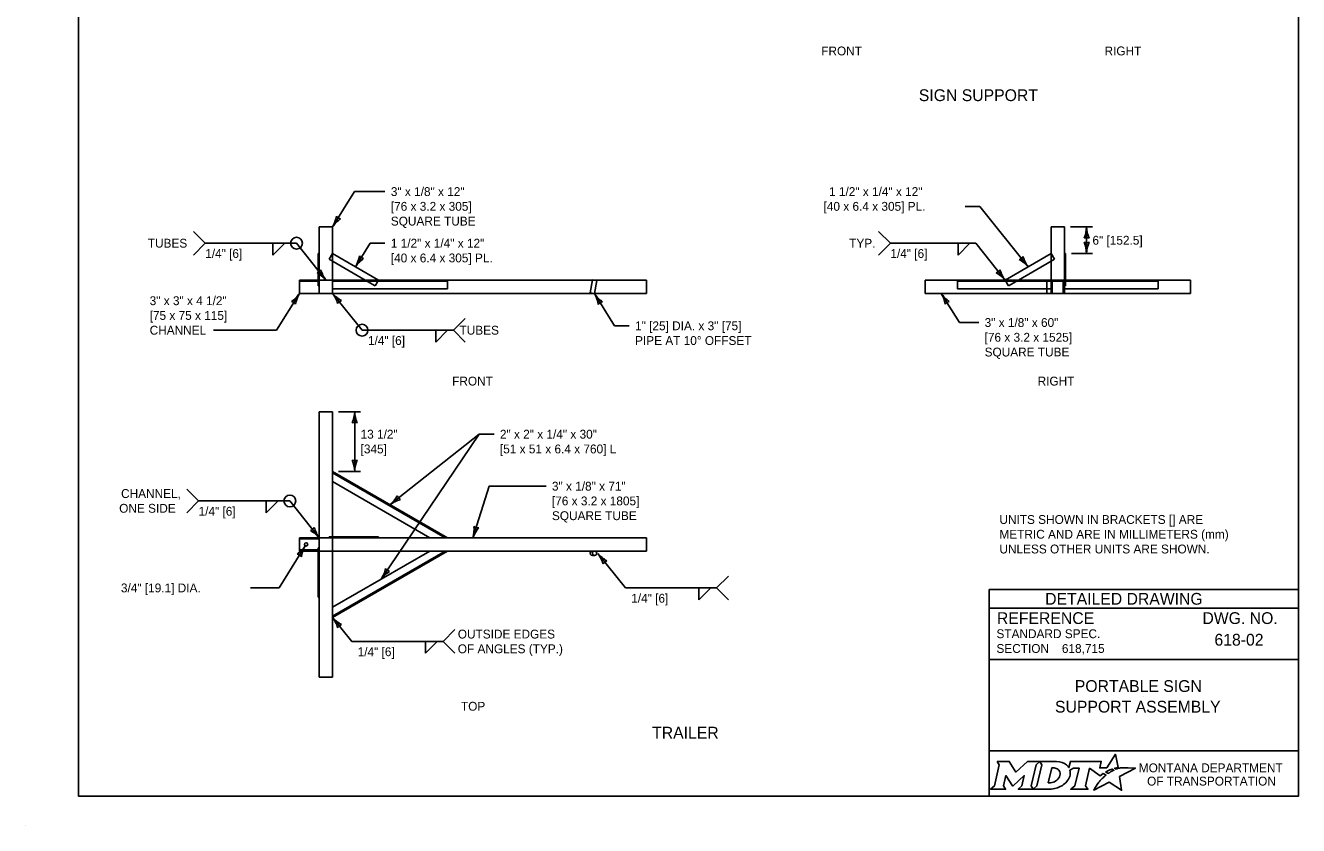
# Model space of a CAD drawing. Extents: x 49991.4 to 50021, y 49987.6 to 50011.4.
# Drawn here: x 49999.98 to 50008.61, y 49999.86 to 50005.29 of the extents above; entities that cross this region are included whole.
import ezdxf

# ---------------------------------------------------------------- set-up
doc = ezdxf.new("R2010")
doc.units = 0
for name, color, linetype in [('Level 1', 7, 'Continuous'), ('Level 2', 7, 'Continuous'), ('Level 3', 7, 'Continuous'), ('Level 4', 7, 'Continuous')]:
    doc.layers.add(name, color=color, linetype=linetype)

msp = doc.modelspace()

# ---------------------------------------------------------------- linework, layer by layer
at = {"layer": 'Level 1'}
for p, q in [((50001.9705, 50003.9214), (50001.9705, 50003.4714)), ((50001.9705, 50003.9214), (50002.0605, 50003.9214)), ((50002.0605, 50003.9214), (50002.0605, 50003.7414)), ((50006.9363, 50003.4714), (50006.9363, 50003.9214)), ((50006.9363, 50003.9214), (50007.0263, 50003.9214)), ((50007.0263, 50003.4714), (50007.0263, 50003.9214)), ((50001.9705, 50003.7414), (50001.9631, 50003.7414)), ((50001.9631, 50003.7414), (50001.9631, 50003.5224)), ((50002.0605, 50003.7414), (50002.0381, 50003.7023)), ((50002.0605, 50003.7414), (50002.3724, 50003.5614)), ((50006.9363, 50003.7414), (50006.6244, 50003.5614)), ((50007.0263, 50003.7414), (50007.0337, 50003.7414)), ((50007.0338, 50003.7414), (50007.0338, 50003.5614)), ((50002.0381, 50003.7023), (50002.2823, 50003.5614)), ((50002.0605, 50003.6894), (50002.0605, 50003.4714)), ((50006.9363, 50003.6894), (50006.7145, 50003.5614)), ((50001.8355, 50003.5614), (50001.8355, 50003.4714)), ((50003.8232, 50003.5614), (50001.8355, 50003.5614)), ((50001.9705, 50003.5224), (50001.9631, 50003.5224)), ((50002.0605, 50003.5014), (50002.8399, 50003.5014)), ((50002.8399, 50003.5014), (50002.8399, 50003.5614)), ((50003.8236, 50003.5633), (50003.8079, 50003.4746)), ((50003.8236, 50003.5633), (50003.8531, 50003.5581)), ((50004.1905, 50003.5614), (50003.8345, 50003.5614)), ((50003.8531, 50003.5581), (50003.8375, 50003.4694)), ((50004.1905, 50003.5614), (50004.1905, 50003.4714)), ((50007.8813, 50003.5614), (50006.0813, 50003.5614)), ((50006.0813, 50003.5614), (50006.0813, 50003.4714)), ((50006.2999, 50003.5014), (50006.2999, 50003.5614)), ((50006.9063, 50003.5014), (50006.2999, 50003.5014)), ((50006.9063, 50003.4714), (50006.9063, 50003.5614)), ((50007.0263, 50003.5014), (50007.6626, 50003.5014)), ((50007.6626, 50003.5014), (50007.6626, 50003.5614)), ((50007.8813, 50003.5614), (50007.8813, 50003.4714)), ((50003.8266, 50003.4714), (50001.8355, 50003.4714)), ((50003.8079, 50003.4746), (50003.8375, 50003.4694)), ((50004.1905, 50003.4714), (50003.8378, 50003.4714)), ((50007.8813, 50003.4714), (50006.0813, 50003.4714)), ((50002.0605, 50002.6686), (50001.9705, 50002.6686)), ((50001.9705, 50002.6686), (50001.9705, 50000.8686)), ((50002.0605, 50000.8686), (50002.0605, 50002.6686)), ((50002.0605, 50002.2636), (50002.8399, 50001.8136)), ((50002.0605, 50002.1944), (50002.7199, 50001.8136)), ((50004.1905, 50001.8136), (50001.8355, 50001.8136)), ((50001.8355, 50001.7236), (50001.8355, 50001.8136)), ((50002.0381, 50001.8211), (50002.0381, 50001.8136)), ((50002.0381, 50001.8211), (50002.3724, 50001.8211)), ((50002.3724, 50001.8211), (50002.3724, 50001.8136)), ((50004.1905, 50001.7236), (50004.1905, 50001.8136)), ((50001.8355, 50001.7236), (50004.1905, 50001.7236)), ((50001.9705, 50001.7461), (50001.9631, 50001.7461)), ((50001.9631, 50001.4118), (50001.9631, 50001.7461)), ((50002.0605, 50001.2736), (50002.8399, 50001.7236)), ((50002.0605, 50001.3429), (50002.7199, 50001.7236)), ((50003.8383, 50001.6936), (50003.8236, 50001.6936)), ((50001.9705, 50001.4118), (50001.9631, 50001.4118)), ((50001.9705, 50000.8686), (50002.0605, 50000.8686)), ((49999.9766, 49999.8624), (49999.9766, 49999.8624))]:
    msp.add_line(p, q, dxfattribs=at)
msp.add_lwpolyline([(50008.6146, 50011.2628), (50000.3356, 50011.2628), (50000.3356, 50000.0624), (50008.6146, 50000.0624)], close=True, dxfattribs=at)
msp.add_circle((50001.8806, 50001.7686), 0.0113, dxfattribs=at)
msp.add_ellipse((50003.8227, 50001.7086), major_axis=(0, 0.015), ratio=0.9848, start_param=6.22507, end_param=9.482803, dxfattribs=at)
msp.add_ellipse((50003.8383, 50001.7086), major_axis=(0, 0.015), ratio=0.9848, dxfattribs=at)
at = {"layer": 'Level 2'}
for p, q in [((50008.6146, 50001.4624), (50006.5146, 50001.4624)), ((50006.5146, 50001.4624), (50006.5146, 50000.0624)), ((50008.6146, 50001.3374), (50006.5146, 50001.3374)), ((50008.2507, 50001.1223), (50008.2507, 50001.1223)), ((50008.6146, 50000.9874), (50006.5146, 50000.9874)), ((50007.0089, 50001.0629), (50007.0089, 50001.0629)), ((50007.5646, 50000.7383), (50007.5646, 50000.7383)), ((50008.6146, 50000.3693), (50006.5146, 50000.3693))]:
    msp.add_line(p, q, dxfattribs=at)
for points in [[(50006.5701, 50000.2974), (50006.5842, 50000.274), (50006.5507, 50000.1307), (50006.525, 50000.1082), (50006.6266, 50000.1082), (50006.6131, 50000.131), (50006.6293, 50000.2011), (50006.673, 50000.1321), (50006.6783, 50000.1321), (50006.7534, 50000.2016), (50006.737, 50000.1305), (50006.7123, 50000.1085), (50006.8139, 50000.1085), (50006.8001, 50000.1318), (50006.8333, 50000.2742)], [(50006.8333, 50000.2742), (50006.8586, 50000.2974), (50006.7762, 50000.2974), (50006.6966, 50000.2244), (50006.6521, 50000.2971), (50006.5701, 50000.2974)], [(50006.9722, 50000.2974), (50006.8586, 50000.2974), (50006.8733, 50000.2745), (50006.8394, 50000.1307), (50006.8139, 50000.1085), (50006.9245, 50000.1085)], [(50007.3771, 50000.2447), (50007.3668, 50000.2503), (50007.3784, 50000.2531), (50007.39, 50000.2551), (50007.3726, 50000.3452), (50007.3131, 50000.2539), (50007.2658, 50000.2532), (50007.2761, 50000.2973), (50007.0669, 50000.2974), (50007.0568, 50000.2549), (50007.051, 50000.2632)], [(50006.9962, 50000.2107), (50006.995, 50000.2026), (50006.9918, 50000.1933), (50006.9876, 50000.1851), (50006.982, 50000.1776), (50006.9755, 50000.1707), (50006.9676, 50000.1644), (50006.9593, 50000.1597), (50006.9502, 50000.1558), (50006.9411, 50000.1535), (50006.9319, 50000.1526), (50006.916, 50000.1526), (50006.9396, 50000.2526), (50006.9556, 50000.2526), (50006.9632, 50000.252), (50006.9708, 50000.2501), (50006.9774, 50000.2471), (50006.9835, 50000.2429), (50006.9883, 50000.2379), (50006.992, 50000.2319), (50006.9947, 50000.2257), (50006.9963, 50000.2183), (50006.9963, 50000.2153), (50006.9962, 50000.2107)], [(50007.0636, 50000.2383), (50007.0882, 50000.2514), (50007.1251, 50000.2514), (50007.0965, 50000.1309), (50007.069, 50000.1082), (50007.1852, 50000.1082), (50007.1682, 50000.1311), (50007.1964, 50000.2513), (50007.2677, 50000.1996), (50007.2888, 50000.2147), (50007.3085, 50000.2038)], [(50007.2527, 50000.1479), (50007.2374, 50000.1235), (50007.2327, 50000.116), (50007.2269, 50000.1074), (50007.2246, 50000.1031), (50007.3299, 50000.1562), (50007.4138, 50000.1011), (50007.4007, 50000.1938), (50007.5076, 50000.2522), (50007.4583, 50000.253), (50007.4282, 50000.2534), (50007.4074, 50000.2537), (50007.4006, 50000.2522), (50007.3957, 50000.251), (50007.3873, 50000.2487), (50007.3771, 50000.2447)], [(50007.3267, 50000.2171), (50007.3243, 50000.2154), (50007.306, 50000.225), (50007.3163, 50000.2307), (50007.3204, 50000.2329), (50007.329, 50000.2369), (50007.3347, 50000.2395), (50007.3426, 50000.2425), (50007.3499, 50000.2452), (50007.3617, 50000.2378), (50007.3577, 50000.2357), (50007.3531, 50000.2332), (50007.3489, 50000.231), (50007.3439, 50000.2281), (50007.342, 50000.227), (50007.3393, 50000.2254), (50007.3368, 50000.224), (50007.3345, 50000.2224), (50007.3319, 50000.2206), (50007.3292, 50000.2188), (50007.3267, 50000.2171)], [(50006.9702, 50000.1158), (50006.9786, 50000.1184), (50006.9916, 50000.1238), (50007.012, 50000.1348)], [(50007.2666, 50000.164), (50007.2666, 50000.164)]]:
    msp.add_lwpolyline(points, dxfattribs=at)
for centre, radius, start, end in [((50006.9953, 50000.219), 0.0709, 339.53292, 15.85821), ((50006.9513, 50000.2363), 0.1183, 300.91025, 339.13831)]:
    msp.add_arc(centre, radius, start, end, dxfattribs=at)
for centre, major_axis, ratio, start_param, end_param in [((50006.9701, 50000.25), (0.0834, -0.0037), 0.568097, 0.61298, 1.570796), ((50007.0257, 50000.2573), (0.0361, -0.0295), 0.469099, 1.225588, 1.570796), ((50007.2974, 50000.1941), (-0.0112, -0.0097), 0.021651, 3.157348, 6.283185), ((50006.9248, 50000.2568), (0, 0.1484), 0.987302, 3.139398, 3.456847), ((50007.2597, 50000.1559), (-0.00694, -0.00806), 0.008222, 0, 3.137361), ((50007.2764, 50000.1742), (-0.0098, -0.0102), 0.016458, 3.141593, 6.279097)]:
    msp.add_ellipse(centre, major_axis=major_axis, ratio=ratio, start_param=start_param, end_param=end_param, dxfattribs=at)
at = {"layer": 'Level 3'}
for p, q in [((50002.2096, 50004.1614), (50002.0605, 50003.9214)), ((50002.2096, 50004.1614), (50002.4157, 50004.1614)), ((50006.3528, 50004.0614), (50006.4528, 50004.0614)), ((50006.7804, 50003.6514), (50006.4528, 50004.0614)), ((50007.0663, 50003.9214), (50007.2163, 50003.9214)), ((50007.1763, 50003.7414), (50007.1763, 50003.9214)), ((50001.1162, 50003.8914), (50001.1962, 50003.8114)), ((50005.7651, 50003.8914), (50005.8451, 50003.8114)), ((50001.1162, 50003.7314), (50001.1962, 50003.8114)), ((50001.1962, 50003.8114), (50001.8157, 50003.8114)), ((50001.6557, 50003.8114), (50001.6557, 50003.7314)), ((50001.6557, 50003.7314), (50001.7357, 50003.8114)), ((50002.0155, 50003.5614), (50001.8157, 50003.8114)), ((50002.3157, 50003.8114), (50002.2164, 50003.6514)), ((50002.3157, 50003.8114), (50002.4157, 50003.8114)), ((50005.7651, 50003.7314), (50005.8451, 50003.8114)), ((50005.8451, 50003.8114), (50006.4246, 50003.8114)), ((50006.3046, 50003.8114), (50006.3046, 50003.7314)), ((50006.3046, 50003.7314), (50006.3846, 50003.8114)), ((50006.6244, 50003.5614), (50006.4246, 50003.8114)), ((50007.0738, 50003.7414), (50007.2163, 50003.7414)), ((50001.8355, 50003.4714), (50001.6803, 50003.2214)), ((50002.2604, 50003.2214), (50002.0605, 50003.4714)), ((50003.8375, 50003.4694), (50003.9729, 50003.2514)), ((50006.1906, 50003.4714), (50006.3136, 50003.2734)), ((50002.8799, 50003.2214), (50002.9599, 50003.3014)), ((50004.0729, 50003.2514), (50003.9729, 50003.2514)), ((50006.4446, 50003.2734), (50006.3136, 50003.2734)), ((50001.6803, 50003.2214), (50001.2533, 50003.2214)), ((50002.2604, 50003.2214), (50002.8799, 50003.2214)), ((50002.7599, 50003.2214), (50002.7599, 50003.1414)), ((50002.7599, 50003.1414), (50002.8399, 50003.2214)), ((50002.8799, 50003.2214), (50002.9599, 50003.1414)), ((50002.1005, 50002.6686), (50002.2505, 50002.6686)), ((50002.2105, 50002.2636), (50002.2105, 50002.6686)), ((50003.0559, 50002.5161), (50002.3902, 50001.5333)), ((50003.0559, 50002.5161), (50002.4502, 50002.0386)), ((50003.1559, 50002.5161), (50003.0559, 50002.5161)), ((50002.1005, 50002.2636), (50002.2505, 50002.2636)), ((50001.0712, 50002.1436), (50001.1512, 50002.0636)), ((50003.1233, 50002.1636), (50003.013, 50001.8136)), ((50003.5088, 50002.1636), (50003.1233, 50002.1636)), ((50001.0712, 50001.9836), (50001.1512, 50002.0636)), ((50001.1512, 50002.0636), (50001.7707, 50002.0636)), ((50001.6107, 50002.0636), (50001.6107, 50001.9836)), ((50001.6107, 50001.9836), (50001.6907, 50002.0636)), ((50001.9705, 50001.8136), (50001.7707, 50002.0636)), ((50001.8746, 50001.7591), (50001.6973, 50001.4736)), ((50004.0469, 50001.4736), (50003.8609, 50001.7064)), ((50004.6664, 50001.4736), (50004.7464, 50001.5536)), ((50001.6973, 50001.4736), (50001.5033, 50001.4736)), ((50004.0469, 50001.4736), (50004.6664, 50001.4736)), ((50004.5464, 50001.4736), (50004.5464, 50001.3936)), ((50004.5464, 50001.3936), (50004.6264, 50001.4736)), ((50004.6664, 50001.4736), (50004.7464, 50001.3936)), ((50002.1906, 50001.1108), (50002.0605, 50001.2736)), ((50002.8101, 50001.1108), (50002.8901, 50001.1908)), ((50002.1906, 50001.1108), (50002.8101, 50001.1108)), ((50002.6901, 50001.1108), (50002.6901, 50001.0308)), ((50002.6901, 50001.0308), (50002.7701, 50001.1108)), ((50002.8101, 50001.1108), (50002.8901, 50001.0308))]:
    msp.add_line(p, q, dxfattribs=at)
for centre in [(50001.8157, 50003.8114), (50002.2604, 50003.2214), (50001.7707, 50002.0636)]:
    msp.add_circle(centre, 0.04, dxfattribs=at)
for centre, radius, start, end in [((50001.8567, 50004.0344), 0.233, 330.98485, 350.2347), ((50002.2444, 50003.7964), 0.2223, 125.61355, 145.79706), ((50002.1281, 50004.0303), 0.0548, 220.29636, 256.01872), ((50006.9542, 50003.9306), 0.2223, 337.45601, 357.63952), ((50007.409, 50003.9329), 0.233, 182.82731, 202.07716), ((50007.1763, 50003.7932), 0.0548, 72.13882, 107.86118), ((50007.1763, 50003.8696), 0.0548, 252.13882, 287.86118), ((50006.9436, 50003.7299), 0.233, 2.82731, 22.07716), ((50007.3984, 50003.7322), 0.2223, 157.45601, 177.63952), ((50002.0126, 50003.7644), 0.233, 331.00254, 350.25239), ((50002.4003, 50003.5265), 0.2223, 125.63124, 145.81475), ((50002.284, 50003.7604), 0.0548, 220.31405, 256.03641), ((50006.7003, 50003.7516), 0.0548, 290.76824, 326.4906), ((50006.6058, 50003.4972), 0.233, 41.45673, 60.70658), ((50006.9596, 50003.7829), 0.2223, 196.08543, 216.26894), ((50001.9354, 50003.6615), 0.0548, 290.77649, 326.49885), ((50001.8409, 50003.4071), 0.233, 41.46498, 60.71483), ((50002.1947, 50003.6929), 0.2223, 196.09368, 216.27719), ((50006.5444, 50003.6616), 0.0548, 290.77067, 326.49303), ((50006.4498, 50003.4071), 0.233, 41.45916, 60.70901), ((50006.8036, 50003.6929), 0.2223, 196.08786, 216.27137), ((50001.6516, 50003.5964), 0.2223, 305.61938, 325.80289), ((50001.7679, 50003.3625), 0.0548, 40.30219, 76.02455), ((50002.0393, 50003.3584), 0.233, 150.99068, 170.24053), ((50001.8813, 50003.3399), 0.2223, 16.09368, 36.27719), ((50002.2351, 50003.6257), 0.233, 221.46498, 240.71483), ((50002.1406, 50003.3713), 0.0548, 110.77649, 146.49885), ((50003.644, 50003.36), 0.2223, 9.29496, 29.47847), ((50004.0291, 50003.6019), 0.233, 214.66626, 233.91611), ((50003.9051, 50003.3605), 0.0548, 103.97777, 139.70013), ((50005.9971, 50003.362), 0.2223, 9.29496, 29.47847), ((50006.3822, 50003.6039), 0.233, 214.66626, 233.91611), ((50006.2582, 50003.3625), 0.0548, 103.97777, 139.70013), ((50001.9884, 50002.6778), 0.2223, 337.45601, 357.63952), ((50002.4432, 50002.6801), 0.233, 182.82731, 202.07716), ((50002.2105, 50002.5404), 0.0548, 72.13882, 107.86118), ((50002.2105, 50002.3918), 0.0548, 252.13882, 287.86118), ((50001.9778, 50002.2521), 0.233, 2.82731, 22.07716), ((50002.4326, 50002.2544), 0.2223, 157.45601, 177.63952), ((50002.2971, 50002.2142), 0.233, 311.07757, 330.32742), ((50002.5805, 50001.8585), 0.2223, 105.70627, 125.88978), ((50002.5509, 50002.118), 0.0548, 200.38908, 236.11144), ((50001.8904, 50001.9137), 0.0548, 290.77649, 326.49885), ((50001.7959, 50001.6593), 0.233, 41.46498, 60.71483), ((50002.1497, 50001.9451), 0.2223, 196.09368, 216.27719), ((50002.7876, 50001.8726), 0.233, 345.33544, 4.58529), ((50003.2221, 50001.7381), 0.2223, 139.96414, 160.14765), ((50003.0515, 50001.9359), 0.0548, 234.64695, 270.36931), ((50001.6907, 50001.884), 0.2223, 305.61938, 325.80289), ((50002.0784, 50001.6461), 0.233, 150.99068, 170.24053), ((50001.807, 50001.6502), 0.0548, 40.30219, 76.02455), ((50003.6817, 50001.5749), 0.2223, 16.09368, 36.27719), ((50004.0355, 50001.8607), 0.233, 221.46498, 240.71483), ((50002.1931, 50001.6575), 0.233, 327.77943, 347.02928), ((50002.5668, 50001.3982), 0.2223, 122.40813, 142.59164), ((50002.4638, 50001.6382), 0.0548, 217.09094, 252.8133), ((50003.941, 50001.6063), 0.0548, 110.77649, 146.49885), ((50001.8813, 50001.1421), 0.2223, 16.09368, 36.27719), ((50002.2351, 50001.4279), 0.233, 221.46498, 240.71483), ((50002.1406, 50001.1735), 0.0548, 110.77649, 146.49885)]:
    msp.add_arc(centre, radius, start, end, dxfattribs=at)
at = {"layer": 'Level 4'}
for p, q in [((50002.0605, 50003.7414), (50002.0605, 50003.6894)), ((50006.9363, 50003.7414), (50006.9587, 50003.7023)), ((50001.9705, 50003.7023), (50001.9631, 50003.7023)), ((50006.9587, 50003.7023), (50006.9363, 50003.6894)), ((50007.0263, 50003.7023), (50007.0337, 50003.7023)), ((50001.9705, 50003.5539), (50001.8355, 50003.5539)), ((50001.8693, 50003.5614), (50001.8693, 50003.5539)), ((50001.8918, 50003.5614), (50001.8918, 50003.5539)), ((50002.0605, 50003.5539), (50002.8399, 50003.5539)), ((50002.2823, 50003.5614), (50002.3498, 50003.5224)), ((50002.3724, 50003.5614), (50002.3498, 50003.5224)), ((50003.8232, 50003.5614), (50003.8345, 50003.5614)), ((50006.2999, 50003.5539), (50006.9363, 50003.5539)), ((50006.6244, 50003.5614), (50006.647, 50003.5224)), ((50006.7145, 50003.5614), (50006.647, 50003.5224)), ((50006.9363, 50003.5014), (50006.9063, 50003.5014)), ((50007.0187, 50003.5539), (50006.9437, 50003.5539)), ((50006.9437, 50003.4714), (50006.9437, 50003.5539)), ((50007.0187, 50003.4714), (50007.0187, 50003.5539)), ((50007.6626, 50003.5539), (50007.0263, 50003.5539)), ((50007.0263, 50003.5224), (50007.0338, 50003.5224)), ((50007.0338, 50003.5614), (50007.0338, 50003.5224)), ((50003.8266, 50003.4714), (50003.8378, 50003.4714)), ((50002.0605, 50002.255), (50002.8249, 50001.8136)), ((50001.9705, 50001.8061), (50001.8355, 50001.8061)), ((50002.3498, 50001.8211), (50002.3498, 50001.8136)), ((50001.8355, 50001.7311), (50001.9705, 50001.7311)), ((50002.0605, 50001.2823), (50002.8249, 50001.7236)), ((50001.9705, 50001.4344), (50001.9631, 50001.4344))]:
    msp.add_line(p, q, dxfattribs=at)

# ---------------------------------------------------------------- texts
at = {"layer": 'Level 2'}
for s, height, p in [('FRONT', 0.06, (50005.3759, 50005.0851)), ('RIGHT', 0.06, (50007.2983, 50005.0851)), ('SIGN SUPPORT', 0.08, (50006.0381, 50004.7751)), ('3" x 1/8" x 12"', 0.06, (50002.4557, 50004.1314)), (' 1 1/2" x 1/4" x 12"', 0.06, (50005.4066, 50004.1314)), ('[76 x 3.2 x 305]', 0.06, (50002.4557, 50004.0314)), ('[40 x 6.4 x 305] PL.', 0.06, (50005.3919, 50004.0314)), ('SQUARE TUBE', 0.06, (50002.4557, 50003.9314)), ('TUBES', 0.06, (50000.8067, 50003.7814)), ('1 1/2" x 1/4" x 12"', 0.06, (50002.4557, 50003.7814)), ('TYP.', 0.06, (50005.5658, 50003.7814)), ('6" [152.5]', 0.06, (50007.2163, 50003.8014)), ('1/4" [6]', 0.06, (50001.1962, 50003.7114)), ('[40 x 6.4 x 305] PL.', 0.06, (50002.4557, 50003.6814)), ('1/4" [6]', 0.06, (50005.8451, 50003.7114)), ('3" x 3" x 4 1/2" ', 0.06, (50000.8193, 50003.3914)), ('[75 x 75 x 115] ', 0.06, (50000.8193, 50003.2914)), ('CHANNEL', 0.06, (50000.8193, 50003.1914)), ('TUBES', 0.06, (50002.9218, 50003.1914)), ('1" [25] DIA. x 3" [75]', 0.06, (50004.1129, 50003.2214)), ('3" x 1/8" x 60"', 0.06, (50006.4846, 50003.2434)), ('1/4" [6]', 0.06, (50002.3004, 50003.1214)), ('PIPE AT 10° OFFSET', 0.06, (50004.1129, 50003.1214)), ('[76 x 3.2 x 1525]', 0.06, (50006.4846, 50003.1434)), ('SQUARE TUBE', 0.06, (50006.4846, 50003.0434)), ('FRONT', 0.06, (50002.8717, 50002.8463)), ('RIGHT', 0.06, (50006.8443, 50002.8463)), ('13 1/2"', 0.06, (50002.2505, 50002.4861)), ('2" x 2" x 1/4" x 30"', 0.06, (50003.1959, 50002.4861)), ('[345]', 0.06, (50002.2505, 50002.3861)), ('[51 x 51 x 6.4 x 760] L', 0.06, (50003.1959, 50002.3861)), ('3" x 1/8" x 71"', 0.06, (50003.5488, 50002.1336)), ('CHANNEL,', 0.06, (50000.6254, 50002.0836)), ('ONE SIDE', 0.06, (50000.6125, 50001.9836)), ('1/4" [6]', 0.06, (50001.1512, 50001.9636)), ('[76 x 3.2 x 1805]', 0.06, (50003.5488, 50002.0336)), ('SQUARE TUBE', 0.06, (50003.5488, 50001.9336)), ('UNITS SHOWN IN BRACKETS [] ARE ', 0.06, (50006.585, 50001.9076)), ('METRIC AND ARE IN MILLIMETERS (mm) ', 0.06, (50006.585, 50001.8076)), ('UNLESS OTHER UNITS ARE SHOWN.', 0.06, (50006.585, 50001.7076)), ('3/4" [19.1] DIA.', 0.06, (50000.6243, 50001.4436)), ('1/4" [6]', 0.06, (50004.0869, 50001.3736)), ('DETAILED DRAWING', 0.0799, (50006.8956, 50001.3599)), ('REFERENCE', 0.08, (50006.5682, 50001.229)), ('DWG. NO.', 0.08, (50007.9624, 50001.229)), ('OUTSIDE EDGES', 0.06, (50002.9101, 50001.1308)), ('STANDARD SPEC.', 0.06, (50006.5649, 50001.133)), ('618-02', 0.08, (50008.0441, 50001.0823)), ('1/4" [6]', 0.06, (50002.2306, 50001.0108)), ('OF ANGLES (TYP.)', 0.06, (50002.9101, 50001.0308)), ('SECTION', 0.06, (50006.5649, 50001.033)), ('618,715', 0.06, (50007.0089, 50001.0329)), ('PORTABLE SIGN', 0.08, (50007.0965, 50000.7683)), ('TOP', 0.06, (50002.9316, 50000.6411)), ('SUPPORT ASSEMBLY', 0.08, (50006.9621, 50000.6283)), ('TRAILER', 0.08, (50004.2286, 50000.4519)), ('MONTANA DEPARTMENT', 0.06, (50007.5308, 50000.2236)), ('OF TRANSPORTATION', 0.06, (50007.587, 50000.1336))]:
    msp.add_text(s, height=height, dxfattribs=at).set_placement(p)

doc.saveas('drawing.dxf')
